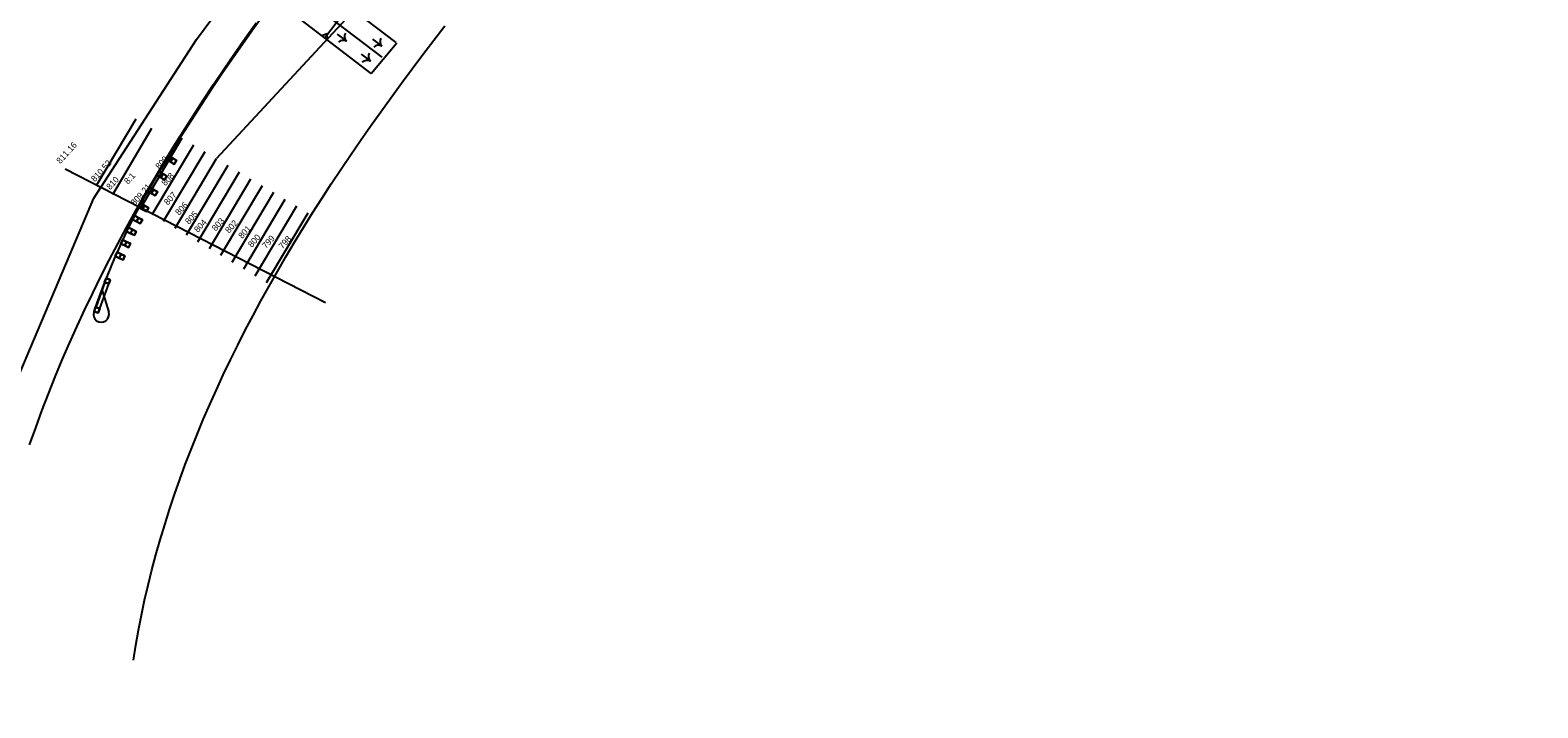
# Model space of a CAD drawing. Extents: x 1465887 to 1476191, y 569684 to 581027.
# Drawn here: x 1469836.1 to 1470175.8, y 573798.1 to 573950.9 of the extents above; entities that cross this region are included whole.
import ezdxf

# ---------------------------------------------------------------- set-up
doc = ezdxf.new("R2010")
doc.units = 0
for name, color, linetype in [('BR_P_Gen_Ground_Slope', 7, 'Continuous'), ('Default', 7, 'Continuous'), ('DR_P_Ditch', 7, 'Continuous'), ('DR_P_Erosion_Control', 7, 'Continuous'), ('PV_X_Driveway', 7, 'Continuous'), ('RD_P_Anchor_Assembly', 7, 'Continuous'), ('SC_Scratch1', 7, 'Continuous')]:
    doc.layers.add(name, color=color, linetype=linetype)

msp = doc.modelspace()

# ---------------------------------------------------------------- linework, layer by layer
at = {"layer": 'BR_P_Gen_Ground_Slope'}
for p, q in [((1469916.06, 573962.98), (1469878.07, 573922.03)), ((1469851.1, 573916.03), (1469859.91, 573930.93)), ((1469854.68, 573913.91), (1469863.49, 573928.81)), ((1469860.45, 573911.22), (1469869.8, 573926.95)), ((1469860.98, 573910.9), (1469870.34, 573926.64)), ((1469863.56, 573909.37), (1469872.91, 573925.1)), ((1469866.13, 573907.84), (1469875.49, 573923.57)), ((1469868.71, 573906.3), (1469878.07, 573922.03)), ((1469871.29, 573904.77), (1469880.65, 573920.5)), ((1469873.87, 573903.24), (1469883.23, 573918.97)), ((1469876.45, 573901.7), (1469885.81, 573917.43)), ((1469879.03, 573900.17), (1469888.38, 573915.9)), ((1469881.6, 573898.63), (1469890.96, 573914.37)), ((1469884.18, 573897.1), (1469893.54, 573912.83)), ((1469886.76, 573895.57), (1469896.12, 573911.3)), ((1469889.34, 573894.03), (1469898.7, 573909.77))]:
    msp.add_line(p, q, dxfattribs=at)
at = {"layer": 'Default'}
msp.add_lwpolyline([(1469867.09, 573922.18), (1469867.81, 573923.36), (1469870.08, 573927.01), (1469872.39, 573930.64), (1469874.73, 573934.25), (1469877.1, 573937.84), (1469879.51, 573941.42), (1469881.94, 573944.97), (1469884.41, 573948.51), (1469886.91, 573952.03), (1469889.43, 573955.53), (1469891.98, 573959.02), (1469894.55, 573962.49), (1469897.15, 573965.94), (1469899.77, 573969.38), (1469902.42, 573972.81), (1469903.75, 573974.52)], dxfattribs=at)
at = {"layer": 'DR_P_Ditch'}
msp.add_line((1469915.36, 573944.87), (1469891.08, 573963.33), dxfattribs=at)
at = {"layer": 'DR_P_Erosion_Control'}
for p, q in [((1469918.57, 573948.14), (1469896.8, 573964.82)), ((1469912.88, 573941.14), (1469891.32, 573957.67)), ((1469902.41, 573949.15), (1469907.89, 573956.3)), ((1469905.24, 573950.05), (1469907.35, 573948.43)), ((1469912.88, 573941.14), (1469918.69, 573948.05)), ((1469913.23, 573948.92), (1469915.34, 573947.31)), ((1469910.63, 573945.52), (1469912.73, 573943.91))]:
    msp.add_line(p, q, dxfattribs=at)
msp.add_lwpolyline([(1469901.79, 573949.62), (1469903.04, 573948.69), (1469902.99, 573950.07)], close=True, dxfattribs=at)
for centre, start, end in [((1469908.4, 573949.51), 150.2525, 225.5141), ((1469906.58, 573947.13), 59.558, 134.8196), ((1469914.57, 573946.01), 59.558, 134.8196), ((1469916.39, 573948.39), 150.2525, 225.5141), ((1469911.97, 573942.61), 59.558, 134.8196), ((1469913.79, 573944.98), 150.2525, 225.5141)]:
    msp.add_arc(centre, 1.51, start, end, dxfattribs=at)
at = {"layer": 'PV_X_Driveway'}
msp.add_lwpolyline([(1470490.67, 573700.83), (1470479.86, 573658.1), (1470459.64, 573614.53), (1470427.11, 573572.83), (1470388.22, 573539.31), (1470336.11, 573515.12), (1470281.02, 573499.93), (1470223.42, 573492.7), (1470166.22, 573493.96), (1470110.42, 573500.92), (1470053.31, 573516.43), (1469999.59, 573537.7), (1469946.66, 573567), (1469899.5, 573602.8), (1469858.29, 573648.66), (1469828.6, 573699.86), (1469815.03, 573750.54), (1469815.08, 573804.7), (1469829.85, 573864.39), (1469850.42, 573913.07), (1469873.55, 573948.79), (1469898.38, 573982.43)], dxfattribs=at)
at = {"layer": 'RD_P_Anchor_Assembly'}
for p, q in [((1469867.09, 573922.18), (1469865.06, 573918.91)), ((1469852.89, 573894.09), (1469850.86, 573888.43)), ((1469853.74, 573893.76), (1469851.71, 573888.15)), ((1469852.21, 573892.44), (1469853.76, 573887.34))]:
    msp.add_line(p, q, dxfattribs=at)
for points in [[(1469867.35, 573922.6), (1469866.83, 573921.76), (1469867.67, 573921.25), (1469868.19, 573922.08)], [(1469868.19, 573922.08), (1469867.67, 573921.25), (1469866.83, 573921.76), (1469867.35, 573922.6)], [(1469868.19, 573922.08), (1469867.67, 573921.25), (1469868.51, 573920.73), (1469869.02, 573921.57)], [(1469869.02, 573921.57), (1469868.51, 573920.73), (1469867.67, 573921.25), (1469868.19, 573922.08)], [(1469865.16, 573919.06), (1469864.64, 573918.22), (1469865.48, 573917.7), (1469866, 573918.54)], [(1469866, 573918.54), (1469865.48, 573917.7), (1469864.64, 573918.22), (1469865.16, 573919.06)], [(1469866, 573918.54), (1469865.48, 573917.7), (1469866.32, 573917.18), (1469866.83, 573918.02)], [(1469866.83, 573918.02), (1469866.32, 573917.18), (1469865.48, 573917.7), (1469866, 573918.54)], [(1469863.03, 573915.47), (1469862.53, 573914.62), (1469863.38, 573914.13), (1469863.88, 573914.97)], [(1469863.88, 573914.97), (1469863.38, 573914.13), (1469862.53, 573914.62), (1469863.03, 573915.47)], [(1469863.88, 573914.97), (1469863.38, 573914.13), (1469864.23, 573913.63), (1469864.73, 573914.48)], [(1469864.73, 573914.48), (1469864.23, 573913.63), (1469863.38, 573914.13), (1469863.88, 573914.97)], [(1469861, 573911.83), (1469860.53, 573910.97), (1469861.39, 573910.5), (1469861.86, 573911.36)], [(1469861.86, 573911.36), (1469861.39, 573910.5), (1469860.53, 573910.97), (1469861, 573911.83)], [(1469861.86, 573911.36), (1469861.39, 573910.5), (1469862.25, 573910.02), (1469862.73, 573910.89)], [(1469862.73, 573910.89), (1469862.25, 573910.02), (1469861.39, 573910.5), (1469861.86, 573911.36)], [(1469858.21, 573906.42), (1469857.78, 573905.53), (1469858.67, 573905.11), (1469859.09, 573906)], [(1469859.09, 573906), (1469858.67, 573905.11), (1469857.78, 573905.53), (1469858.21, 573906.42)], [(1469859.09, 573906), (1469858.67, 573905.11), (1469859.56, 573904.68), (1469859.98, 573905.57)], [(1469859.98, 573905.57), (1469859.56, 573904.68), (1469858.67, 573905.11), (1469859.09, 573906)], [(1469859.61, 573909.12), (1469859.14, 573908.26), (1469860, 573907.79), (1469860.48, 573908.65)], [(1469860.48, 573908.65), (1469860, 573907.79), (1469859.14, 573908.26), (1469859.61, 573909.12)], [(1469860.48, 573908.65), (1469860, 573907.79), (1469860.87, 573907.32), (1469861.34, 573908.18)], [(1469861.34, 573908.18), (1469860.87, 573907.32), (1469860, 573907.79), (1469860.48, 573908.65)], [(1469856.9, 573903.66), (1469856.47, 573902.77), (1469857.36, 573902.35), (1469857.79, 573903.23)], [(1469857.79, 573903.23), (1469857.36, 573902.35), (1469856.47, 573902.77), (1469856.9, 573903.66)], [(1469857.79, 573903.23), (1469857.36, 573902.35), (1469858.25, 573901.92), (1469858.67, 573902.81)], [(1469858.67, 573902.81), (1469858.25, 573901.92), (1469857.36, 573902.35), (1469857.79, 573903.23)], [(1469855.64, 573900.87), (1469855.22, 573899.98), (1469856.11, 573899.56), (1469856.53, 573900.45)], [(1469856.53, 573900.45), (1469856.11, 573899.56), (1469855.22, 573899.98), (1469855.64, 573900.87)], [(1469856.53, 573900.45), (1469856.11, 573899.56), (1469857.01, 573899.14), (1469857.42, 573900.03)], [(1469857.42, 573900.03), (1469857.01, 573899.14), (1469856.11, 573899.56), (1469856.53, 573900.45)], [(1469853.19, 573895.03), (1469852.84, 573894.11), (1469853.75, 573893.75), (1469854.11, 573894.67)], [(1469854.11, 573894.67), (1469853.75, 573893.75), (1469852.84, 573894.11), (1469853.19, 573895.03)], [(1469850.79, 573888.45), (1469850.49, 573887.52), (1469851.42, 573887.21), (1469851.73, 573888.15)], [(1469851.73, 573888.15), (1469851.42, 573887.21), (1469850.49, 573887.52), (1469850.79, 573888.45)]]:
    msp.add_lwpolyline(points, close=True, dxfattribs=at)
for centre, radius, start, end in [((1469997.86, 573838.05), 155.48, 148.6629, 161.5018), ((1469852.08, 573886.83), 1.75, 161.8611, 16.9071)]:
    msp.add_arc(centre, radius, start, end, dxfattribs=at)
at = {"layer": 'SC_Scratch1'}
msp.add_line((1469843.98, 573919.7), (1469902.58, 573889.53), dxfattribs=at)
for points in [[(1469835.94, 573857.41), (1469837.3, 573861.28), (1469838.72, 573865.13), (1469840.19, 573868.97), (1469841.72, 573872.8), (1469843.3, 573876.6), (1469844.94, 573880.39), (1469846.63, 573884.17), (1469848.37, 573887.92), (1469850.16, 573891.66), (1469852, 573895.38), (1469853.88, 573899.09), (1469855.81, 573902.77), (1469857.79, 573906.44), (1469859.8, 573910.09), (1469861.86, 573913.72), (1469863.97, 573917.34), (1469866.11, 573920.94), (1469868.29, 573924.52), (1469870.5, 573928.08), (1469872.76, 573931.63), (1469875.05, 573935.16), (1469877.37, 573938.67), (1469879.73, 573942.17), (1469882.12, 573945.66), (1469884.54, 573949.12), (1469886.98, 573952.58)], [(1469859.31, 573808.88), (1469859.85, 573812.27), (1469860.46, 573815.66), (1469861.12, 573819.05), (1469861.84, 573822.44), (1469862.63, 573825.84), (1469863.48, 573829.24), (1469864.38, 573832.64), (1469865.35, 573836.04), (1469866.37, 573839.44), (1469867.45, 573842.83), (1469868.58, 573846.22), (1469869.77, 573849.62), (1469871.01, 573853), (1469872.31, 573856.39), (1469873.66, 573859.76), (1469875.07, 573863.14), (1469876.52, 573866.51), (1469878.03, 573869.87), (1469879.58, 573873.23), (1469881.19, 573876.58), (1469882.84, 573879.92), (1469884.54, 573883.26), (1469886.28, 573886.59), (1469888.07, 573889.91), (1469889.91, 573893.23), (1469891.78, 573896.54), (1469893.7, 573899.85), (1469895.66, 573903.14), (1469897.67, 573906.43), (1469899.71, 573909.71), (1469901.79, 573912.99), (1469903.91, 573916.26), (1469906.07, 573919.52), (1469908.26, 573922.78), (1469910.49, 573926.03), (1469912.76, 573929.28), (1469915.05, 573932.52), (1469917.39, 573935.76), (1469919.75, 573938.99), (1469922.14, 573942.22), (1469924.57, 573945.44), (1469927.02, 573948.66), (1469929.5, 573951.88)]]:
    msp.add_lwpolyline(points, dxfattribs=at)

# ---------------------------------------------------------------- texts
at = {"layer": 'BR_P_Gen_Ground_Slope'}
for s, p in [('811.16', (1469842.86, 573920.7)), ('810.52', (1469850.65, 573916.62)), ('809', (1469865.17, 573919.45)), ('810', (1469854.09, 573914.83)), ('8:1', (1469858.12, 573916.09)), ('809.21', (1469859.59, 573911.27)), ('808', (1469866.53, 573915.7)), ('807', (1469867.09, 573911.37)), ('806', (1469869.62, 573909.07)), ('805', (1469871.86, 573907.03)), ('804', (1469873.88, 573905.19)), ('803', (1469877.88, 573905.52)), ('802', (1469880.88, 573905.04)), ('801', (1469883.84, 573903.8)), ('800', (1469886.01, 573901.83)), ('799', (1469889.21, 573901.57)), ('798', (1469892.94, 573901.48))]:
    msp.add_text(s, height=1.4, rotation=47.7564, dxfattribs=at).set_placement(p)

doc.saveas('drawing.dxf')
